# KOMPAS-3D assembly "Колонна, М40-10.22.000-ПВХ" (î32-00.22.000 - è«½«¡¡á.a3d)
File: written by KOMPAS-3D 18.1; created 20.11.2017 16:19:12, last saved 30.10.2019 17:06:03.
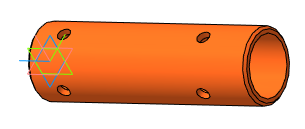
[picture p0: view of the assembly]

Document properties: Автор: Милов; Организация: Милов; Полное имя файла: D:\Magna\Магна Ins\Магна ins 32\М32-00.22.000 - Колонна.a3d

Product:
- Part/product: Колонна  | designation М40-10.22.000-ПВХ  | pos. 0
    Масса: 0.726412
    Раздел спецификации: Сборочные единицы
    Форматы листов документа: A3
    source file: ..\Магна ins 40\Магна Ins 40-L-3-N-ПВХ\М40-10.22.000 - Колонна.cdw
  - Component [detail]: Отбойник  | designation М40-10.22.002-ПВХ  | qty 2  | pos. 2  | Масса: 0.0189589; Раздел спецификации: Детали; Форматы листов документа: A4
  - Component [detail]: Колонна  | designation М40-10.22.001-ПВХ  | pos. 1  | Масса: 0.677738; Раздел спецификации: Детали; Форматы листов документа: A3; Примечание: см. заказ; source file: ..\Магна ins 40\Магна Ins 40-L-3-N-ПВХ\М40-10.22.001 - Колонна.cdw, М32-00.22.001 - Колонна.m3d
- Part/product: Колонна  | designation М32-00.22.000-435  | pos. 0
    Масса: 1.25455
    Раздел спецификации: Сборочные единицы
    Форматы листов документа: A3
  - Component [detail]: Отбойник  | designation М32-00.22.002  | qty 2  | pos. 2  | Масса: 0.0189589; Раздел спецификации: Детали; Форматы листов документа: A4; source file: М32-00.22.002 - Отбойник.cdw, М32-00.22.002 - Отбойник.m3d
  - Component [detail]: Колонна  | designation М32-00.22.001-435  | pos. 1  | Масса: 1.21663; Раздел спецификации: Детали; Форматы листов документа: A3; Примечание: см. заказ
- Part/product: Колонна  | designation М32-00.22.000  | pos. 0
    Масса: 0.990487
    Раздел спецификации: Сборочные единицы
    Форматы листов документа: A3
    source file: М32-00.22.000 - Колонна.cdw
  - Component [detail]: Отбойник  | designation М32-00.22.002  | qty 2  | pos. 2  | Раздел спецификации: Детали; Форматы листов документа: A4; source file: М32-00.22.002 - Отбойник.cdw, М32-00.22.002 - Отбойник.m3d
  - Component [detail]: Колонна  | designation М32-00.22.001  | pos. 1  | Масса: 0.990487; Раздел спецификации: Детали; Форматы листов документа: A3; Примечание: см. заказ; source file: М32-00.22.001 - Колонна.cdw, М32-00.22.001 - Колонна.m3d

Referenced files in D:\Magna\Магна Ins\Магна ins 32\: М32-00.22.002 - Отбойник.cdw, М32-00.22.001 - Колонна.m3d, М32-00.22.001 - Колонна.cdw, М32-00.22.000 - Колонна.cdw
Referenced files in D:\Magna\Магна Ins\Магна ins 40\Магна Ins 40-L-3-N-ПВХ\: М40-10.22.001 - Колонна.cdw
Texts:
  М40-10.22.002 - ПВХ
  М40-10.22.001 - ПВХ
  М40-10.22.001-ПВХ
